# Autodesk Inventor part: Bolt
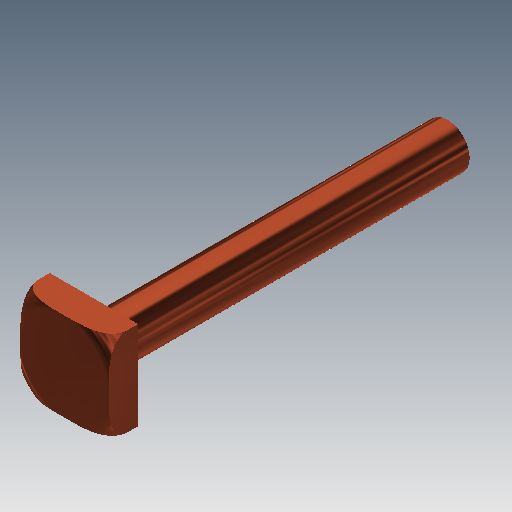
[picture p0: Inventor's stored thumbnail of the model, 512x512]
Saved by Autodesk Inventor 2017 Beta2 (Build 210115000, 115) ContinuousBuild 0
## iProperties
Created: 2009-04
Part Number: Bolt
Document SubType Name: Modeling
Designer: Sham
Density: 8.92 g/cm^3
Material: Copper, Alloy
Appearance: Copper - Satin
Author: Sham
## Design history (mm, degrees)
sketch "Sketch1"
  geometry: L1 (-12, 12)-(12, 12); L2 (12, 12)-(12, -12); L3 (12, -12)-(-12, -12); L4 (-12, -12)-(-12, 12); 1 further point
  constraints: 8 end point, 2 parallel, 2 perpendicular, 1 horizontal, 1 other
  dimensions: "d0" = 24 distance of L1.start L1.end; "d1" = 12 distance from line of L2 point (0, 0); "d2" = 12 distance from line of L1 point (0, 0)
extrude "Extrusion1" new body sketch "Sketch1" distance "d3" = 8; taper "d4" = 0 deg
sketch "Sketch2"
  geometry: C1 r 6 at (0, 0)
  constraints: 1 centre point
  dimensions: "d5" = 12 diameter of C1
extrude "Extrusion2" join sketch "Sketch2" distance "d6" = 96; taper "d7" = 0 deg
workpoint "Work Point1"
workplane "Work Plane1"
sketch "Sketch3"
  geometry: L1 (33.941, 5)-(33.941, 6); L2 (28.941, 0)-(28.405, 0); L3 (16.971, 125.007)-(16.971, -22.043) reference; A1 r 5 centre (28.941, 5) between (28.941, 0) and (33.941, 5); 1 further point
  constraints: 4 end point, 2 point on circle, 2 point on line, 2 tangent, 1 centre point, 1 perpendicular
  dimensions: "d10" = 5 radius of A1
revolve "Revolution1" sketch "Sketch3" stored, may be unused: angle "d12" = 90 deg
body "Solid1"
other parameters: "d11" = 90 deg
